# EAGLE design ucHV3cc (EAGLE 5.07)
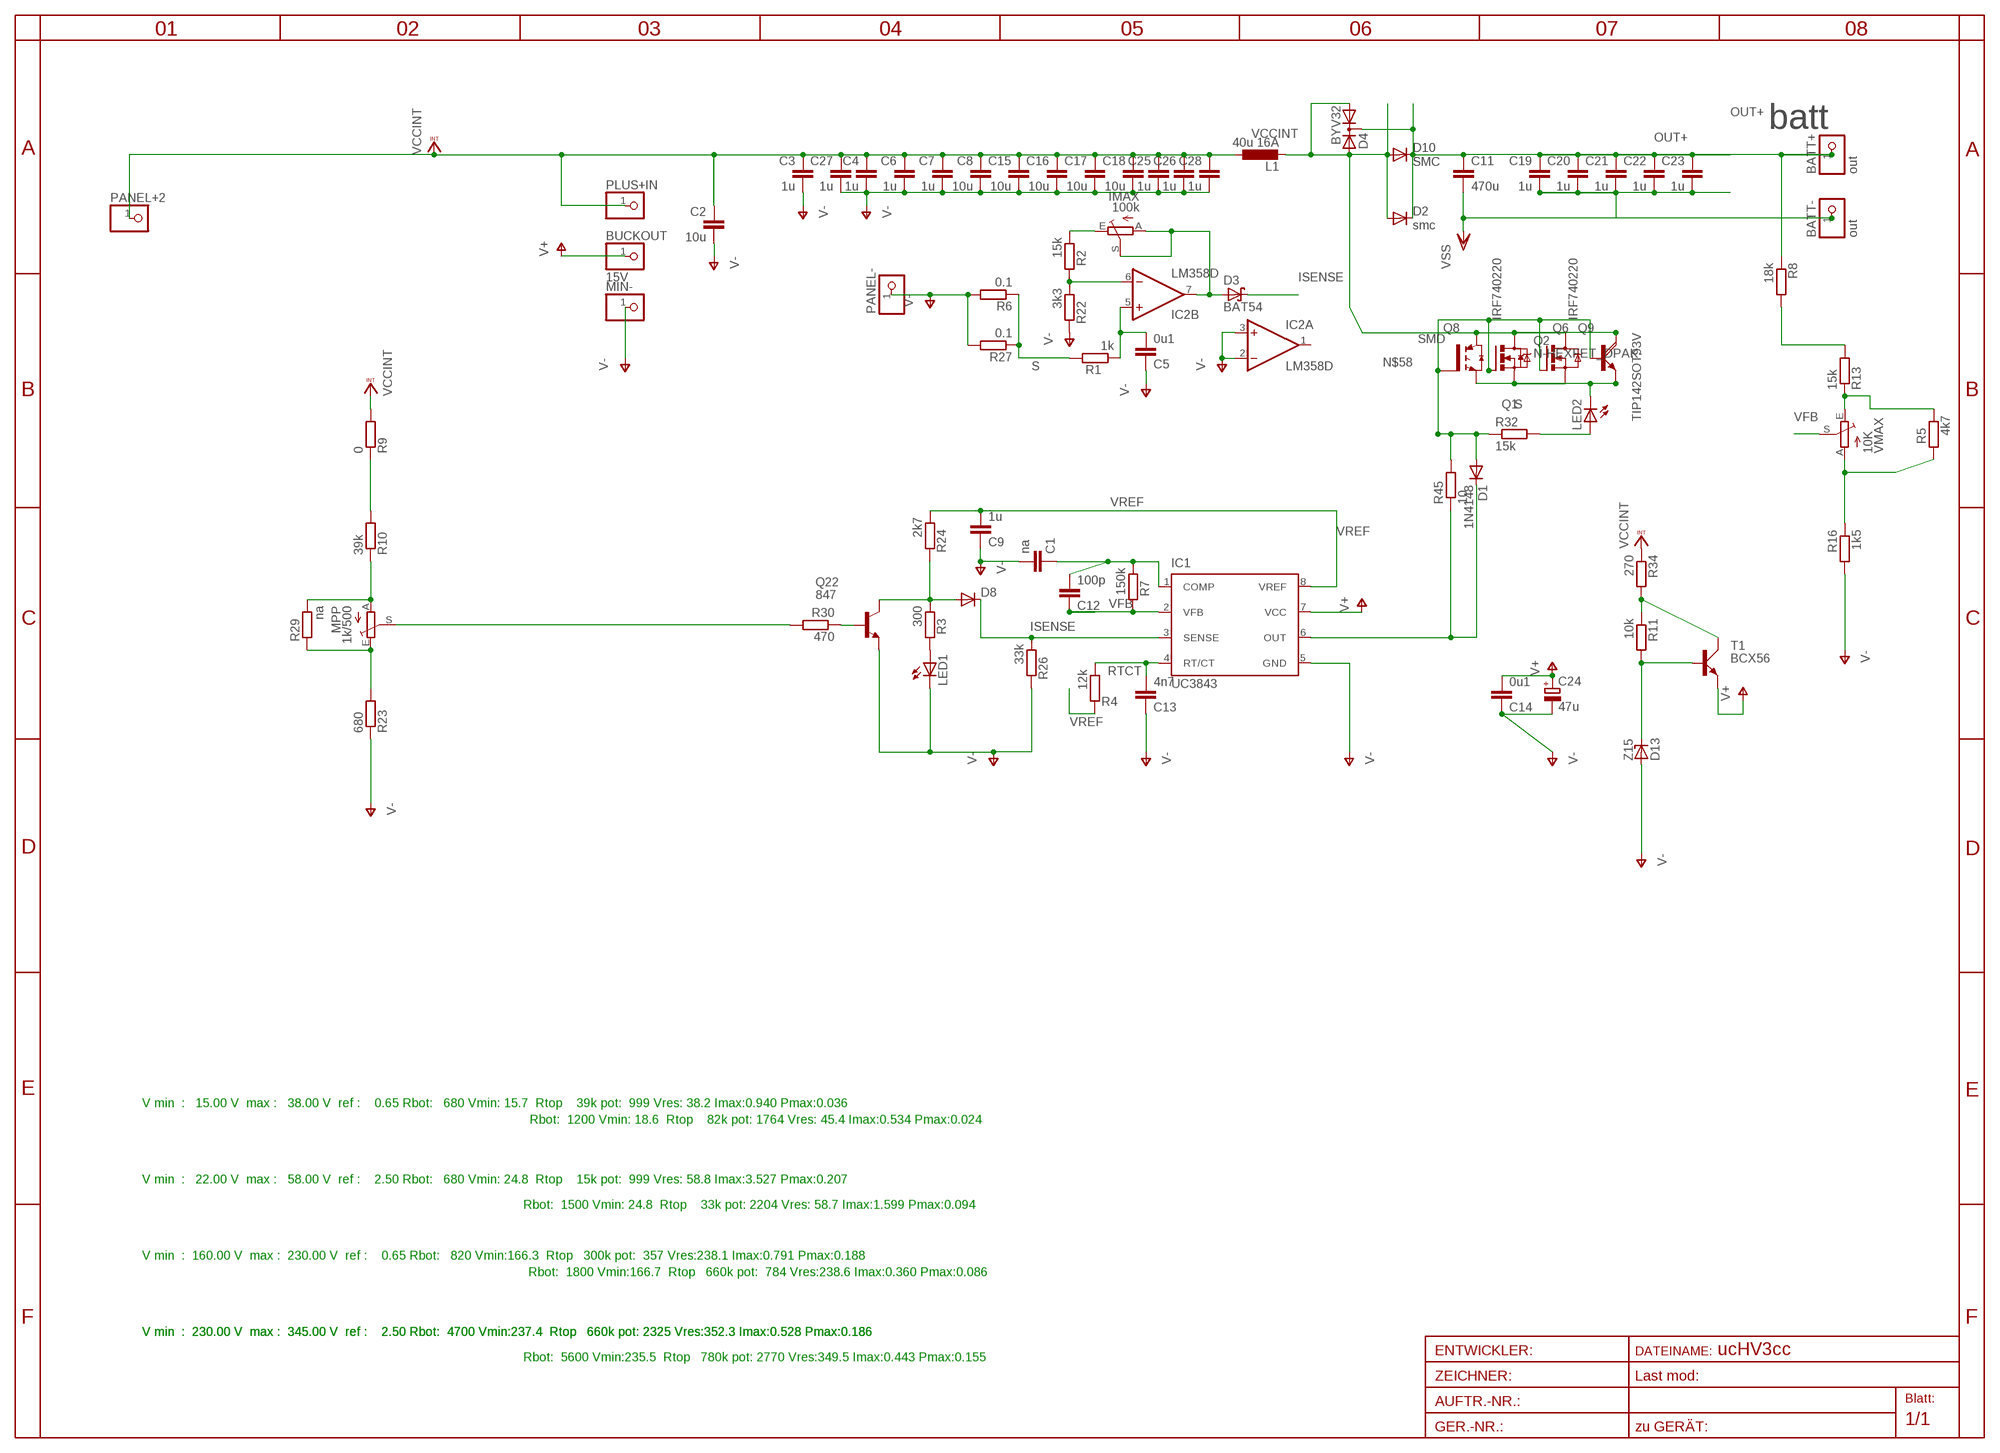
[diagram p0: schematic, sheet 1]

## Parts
BATT+  out  PINHD-1X11MM6  [1X1MM8]
BATT-  out  PINHD-1X11MM6  [1X1MM8]
BUCKOUT  15V  PINHD-1X11MM0  [1X1MM0]
C1  na  C-EUC0805  [C0805]
C2  10u  C-EUC058MLCC  [C058-020X040]
C3  1u  C-EUC058MLCC  [C058-020X040]
C4  1u  C-EUC058MLCC  [C058-020X040]
C5  0u1  C-EUC0805  [C0805]
C6  1u  C-EUC058MLCC  [C058-020X040]
C7  1u  C-EUC058MLCC  [C058-020X040]
C8  10u  C-EUC058MLCC  [C058-020X040]
C9  1u  C-EUC1206  [C1206]
C11  470u  C-EU075-052X106  [C075-052X106]
C12  100p  C-EUC0805  [C0805]
C13  4n7  C-EUC0805  [C0805]
C14  0u1  C-EUC3216  [C3216]
C15  10u  C-EUC058MLCC  [C058-020X040]
C16  10u  C-EUC058MLCC  [C058-020X040]
C17  10u  C-EUC058MLCC  [C058-020X040]
C18  10u  C-EUC058MLCC  [C058-020X040]
C19  1u  C-EUC1206  [C1206]
C20  1u  C-EUC1206  [C1206]
C21  1u  C-EUC1206  [C1206]
C22  1u  C-EUC1206  [C1206]
C23  1u  C-EUC1206  [C1206]
C24  47u  CPOL-EUSANYO_SMD_C6  [SANYO-OSCON_SMD_C6]
C25  1u  C-EUC058MLCC  [C058-020X040]
C26  1u  C-EUC058MLCC  [C058-020X040]
C27  1u  C-EUC058MLCC  [C058-020X040]
C28  1u  C-EUC058MLCC  [C058-020X040]
D1  1N4148  DIODE-MINIMELF  [MINIMELF]
D2  smc  DIODE-SMC  [SMC]
D3  BAT54  [SOT23]
D4  BYV32  [TO220ABS]
D8  DIODE-SOT23  [SOT23]
D10  SMC  DIODE-SMC  [SMC]
D13  Z15  ZENER-DIODESOD80C  [SOD80C]
IC1  UC3843  UC1843D8  [SO-08]
IC2  LM358D  [SO08]
IMAX  100k  TRIM_EU-S64W  [S64W]
L1  40u 16A  L-EU  [RING]
LED1  LEDCHIPLED_1206  [CHIPLED_1206]
LED2  LEDCHIPLED_1206  [CHIPLED_1206]
MIN-  PINHD-1X11MM0  [1X1MM0]
MPP  1k/500  TRIM_EU-S64W  [S64W]
PANEL+2  PINHD-1X11MM6  [1X1MM8]
PANEL-  PINHD-1X11MM6  [1X1MM8]
PLUS+IN  PINHD-1X11MM0  [1X1MM0]
Q1  IRF740220  [TO220BV]
Q2  N-HEXFET_DPAK-  [TO252]
Q6  IRF740220  [TO220BV]
Q8  SMD  IRG4BC15UD-S  [D2PACK]
Q9  TIP142SOT93V  [SOT93V]
Q22  847  BC847ASMD  [SOT23]
R1  1k  R-EU_R0805  [R0805]
R2  15k  R-EU_R0805  [R0805]
R3  300  R-EU_R0805  [R0805]
R4  12k  R-EU_R0805  [R0805]
R5  4k7  R-EU_R0805  [R0805]
R6  0.1  R-EU_0207/10  [0207/10]
R7  150k  R-EU_R0805  [R0805]
R8  18k  R-EU_R1206  [R1206]
R9  0  R-EU_R1206  [R1206]
R10  39k  R-EU_R1206  [R1206]
R11  10k  R-EU_R1206  [R1206]
R13  15k  R-EU_R1206  [R1206]
R16  1k5  R-EU_R0805  [R0805]
R22  3k3  R-EU_R0805  [R0805]
R23  680  R-EU_R0805  [R0805]
R24  2k7  R-EU_R0805  [R0805]
R26  33k  R-EU_R0805  [R0805]
R27  0.1  R-EU_R3216  [R3216]
R29  na  R-EU_R1206  [R1206]
R30  470  R-EU_R0805  [R0805]
R32  15k  R-EU_R0805  [R0805]
R34  270  R-EU_0617/17  [0617/17]
R45  10  R-EU_R0805  [R0805]
T1  BCX56  [SOT223]
VMAX  10K  TRIM_EU-S64W  [S64W]

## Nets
DQ18: D2.A D4.A1 D4.A2 D10.A L1.2 Q1.D Q2.3(D) Q6.D Q8.2(C) Q9.C
ISENSE: D3.3(C) D8.3(C) IC1.3(SENSE) R26.1
N$1: C5.2 IC2.5(B:+IN) R1.1
N$2: IMAX.E R2.1
N$3: Q22.1(B) R30.1
N$4: LED1.A R3.2
N$5: LED2.A R32.2
N$6: R8.2 R13.2
N$7: D13.C R11.2 T1.1(B)
N$18: C1.1 C12.2 IC1.1(COMP) R7.1
N$21: R5.2 R16.1 VMAX.A
N$22: D3.1(A) IC2.7(B:OUT) IMAX.A IMAX.S
N$23: R11.1 R34.2 T1.2(C)
N$25: D1.C IC1.6(OUT) R45.1
N$27: IC2.6(B:-IN) R2.2 R22.1
N$30: R9.1 R10.2
N$32: MPP.A R10.1 R29.1
N$34: MPP.E R23.2 R29.2
N$37: R5.1 R13.1 VMAX.E
N$58: D1.A Q1.G Q2.1(G) Q6.G Q8.1(G) Q9.B R32.1 R45.2
N$71: D8.1(A) Q22.3(C) R3.1 R24.2
OUT+: BATT+.1 C11.1 C19.1 C20.1 C21.1 C22.1 C23.1 D2.C D4.C D10.C R8.1
PRB1: MPP.S R30.2
RTCT: C13.2 IC1.4(RT/CT) R4.1
S: LED2.C Q1.S Q2.2(S) Q6.S Q8.3(E) Q9.E R1.2 R6.1 R27.1
V+: BUCKOUT.1 C14.2 C24.+ IC1.7(VCC) T1.3(E)
V-: BATT-.1 C1.2 C2.2 C3.2 C4.2 C5.1 C6.2 C7.2 C8.2 C9.1 C11.2 C13.1 C14.1 C15.2 C16.2 C17.2 C18.2 C19.2 C20.2 C21.2 C22.2 C23.2 C24.- C25.2 C26.2 C27.2 C28.2 D13.A IC1.5(GND) IC2.2(A:-IN) IC2.3(A:+IN) LED1.C MIN-.1 PANEL-.1 Q22.2(E) R6.2 R16.2 R22.2 R23.1 R26.2 R27.2 ; supply symbol labelled VSS
VCCINT: C2.1 C3.1 C4.1 C6.1 C7.1 C8.1 C15.1 C16.1 C17.1 C18.1 C25.1 C26.1 C27.1 C28.1 L1.1 PANEL+2.1 PLUS+IN.1 R9.2 R34.1
VFB: C12.1 IC1.2(VFB) R7.2 VMAX.S
VREF: C9.2 IC1.8(VREF) R4.2 R24.1
Unconnected: IC2.1(A:OUT)

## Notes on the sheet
- batt
- V min  :   15.00 V  max :   38.00 V  ref :    0.65 Rbot:   680 Vmin: 15.7  Rtop    39k pot:  999 Vres: 38.2 Imax:0.940 Pmax:0.036
- Rbot:  1200 Vmin: 18.6  Rtop    82k pot: 1764 Vres: 45.4 Imax:0.534 Pmax:0.024
- V min  :   22.00 V  max :   58.00 V  ref :    2.50 Rbot:   680 Vmin: 24.8  Rtop    15k pot:  999 Vres: 58.8 Imax:3.527 Pmax:0.207
- Rbot:  1500 Vmin: 24.8  Rtop    33k pot: 2204 Vres: 58.7 Imax:1.599 Pmax:0.094
- V min  :  160.00 V  max :  230.00 V  ref :    0.65 Rbot:   820 Vmin:166.3  Rtop   300k pot:  357 Vres:238.1 Imax:0.791 Pmax:0.188
- Rbot:  1800 Vmin:166.7  Rtop   660k pot:  784 Vres:238.6 Imax:0.360 Pmax:0.086
- V min  :  230.00 V  max :  345.00 V  ref :    2.50 Rbot:  4700 Vmin:237.4  Rtop   660k pot: 2325 Vres:352.3 Imax:0.528 Pmax:0.186 | V min  :  230.00 V  max :  345.00 V  ref :    2.50 Rbot:  4700 Vmin:237.4  Rtop   660k pot: 2325 Vres:352.3 Imax:0.528 Pmax:0.186
- Rbot:  5600 Vmin:235.5  Rtop   780k pot: 2770 Vres:349.5 Imax:0.443 Pmax:0.155

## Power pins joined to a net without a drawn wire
V+: IC2.8(P:V+)
V-: IC2.4(P:V-)

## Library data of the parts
BATT+ BATT- BUCKOUT MIN- PANEL+2 PANEL- PLUS+IN = pinhead:PINHD-1X1: PIN HEADER
C1-C9 C11-C23 C25-C28 = rcl:C-EU: CAPACITOR, European symbol
C24 = rcl:CPOL-EU: POLARIZED CAPACITOR, European symbol
D1 D2 D8 D10 = diode:DIODE-: DIODE
D3 = diode:BAT54: Schottky Diodes
D4 = diode:BYV32: DIODE 2 x Si diode 200 V, 20 A/230 Apeak, 25 ns
D13 = diode:ZENER-DIODE: Z-Diode
IC1 = texas:UC1843D8: PULSE WIDTH MODULATOR
IC2 = linear:LM358: OP AMP also LM158; LM258; LM2904 Source: http://cache.national.com/ds/LM/LM158.pdf
IMAX MPP VMAX = pot:TRIM_EU-: POTENTIOMETER
L1 = rcl:L-EU: INDUCTOR, European symbol
LED1 LED2 = led:LED: LED
Q1 Q6 = transistor-power:IRF740: N-CHANNEL MOS FET
Q2 = transistor-power:N-HEXFET_?-*: HEXFET® Power MOSFET
Q8 = transistor-power:IRG4BC15UD-: INSULATED GATE BIPOLAR TRANSISTOR WITH ULTRAFAST SOFT RECOVERY DIODE
Q9 = transistor-power:TIP142: NPN DARLINGTON TRANSISTOR
Q22 = transistor-npn:BC847*: NPN Transistor
R1-R10 R13 R16 R22-R24 R26 R27 R29 R30 R34 = rcl:R-EU_: RESISTOR, European symbol
R11 R32 R45 = rcl-2:R-EU_: RESISTOR, European symbol
T1 = transistor-power:BCX56

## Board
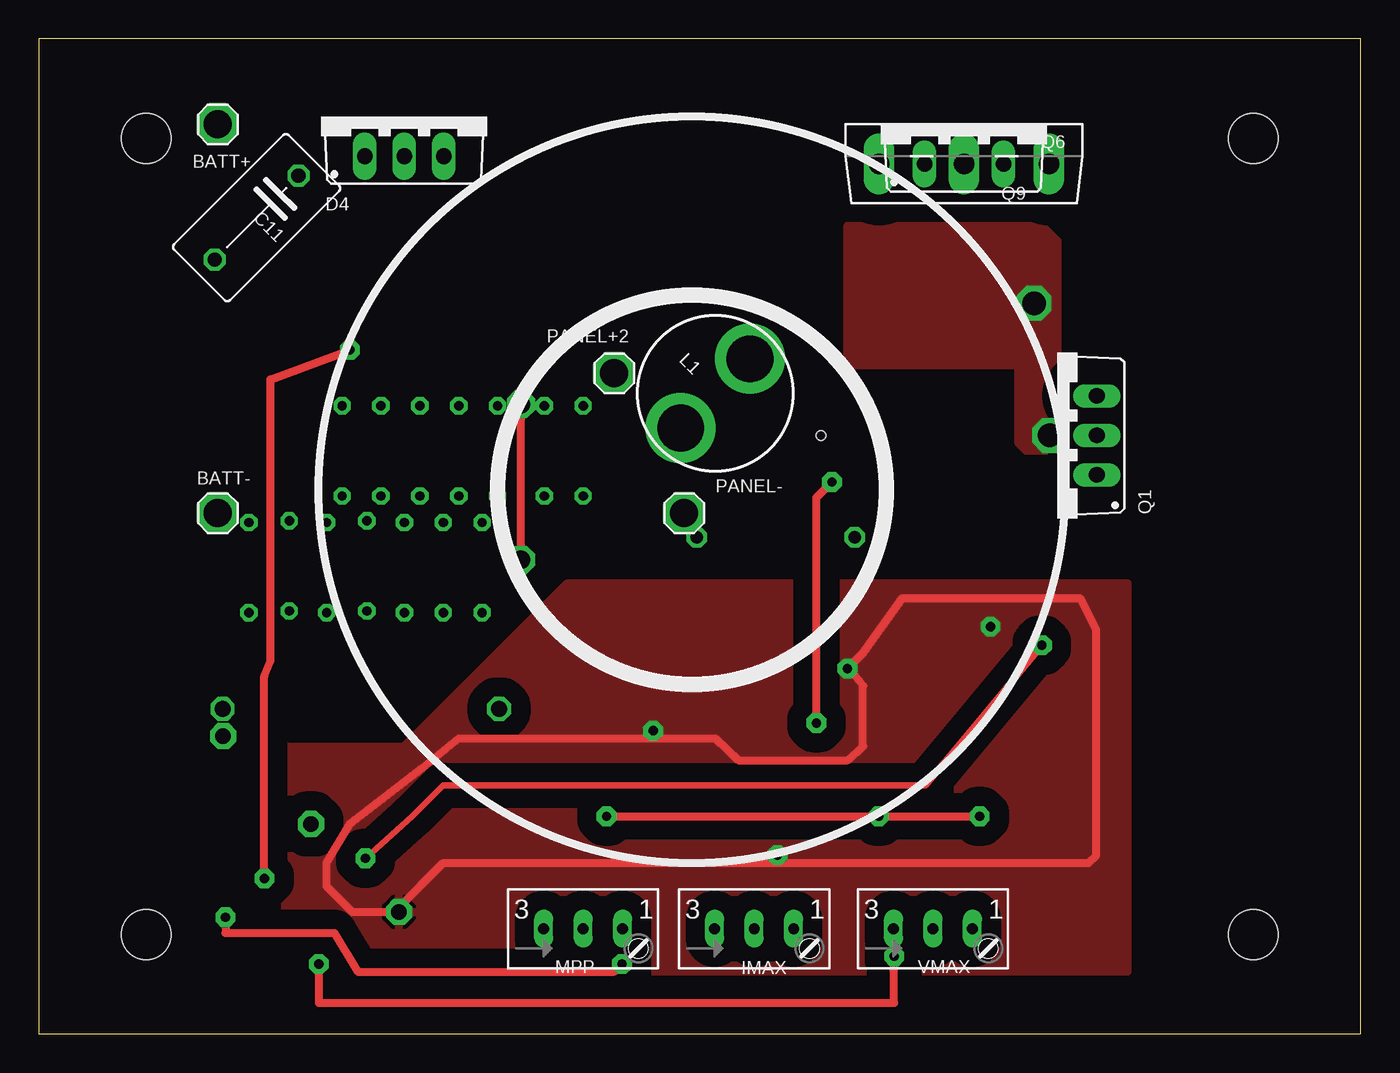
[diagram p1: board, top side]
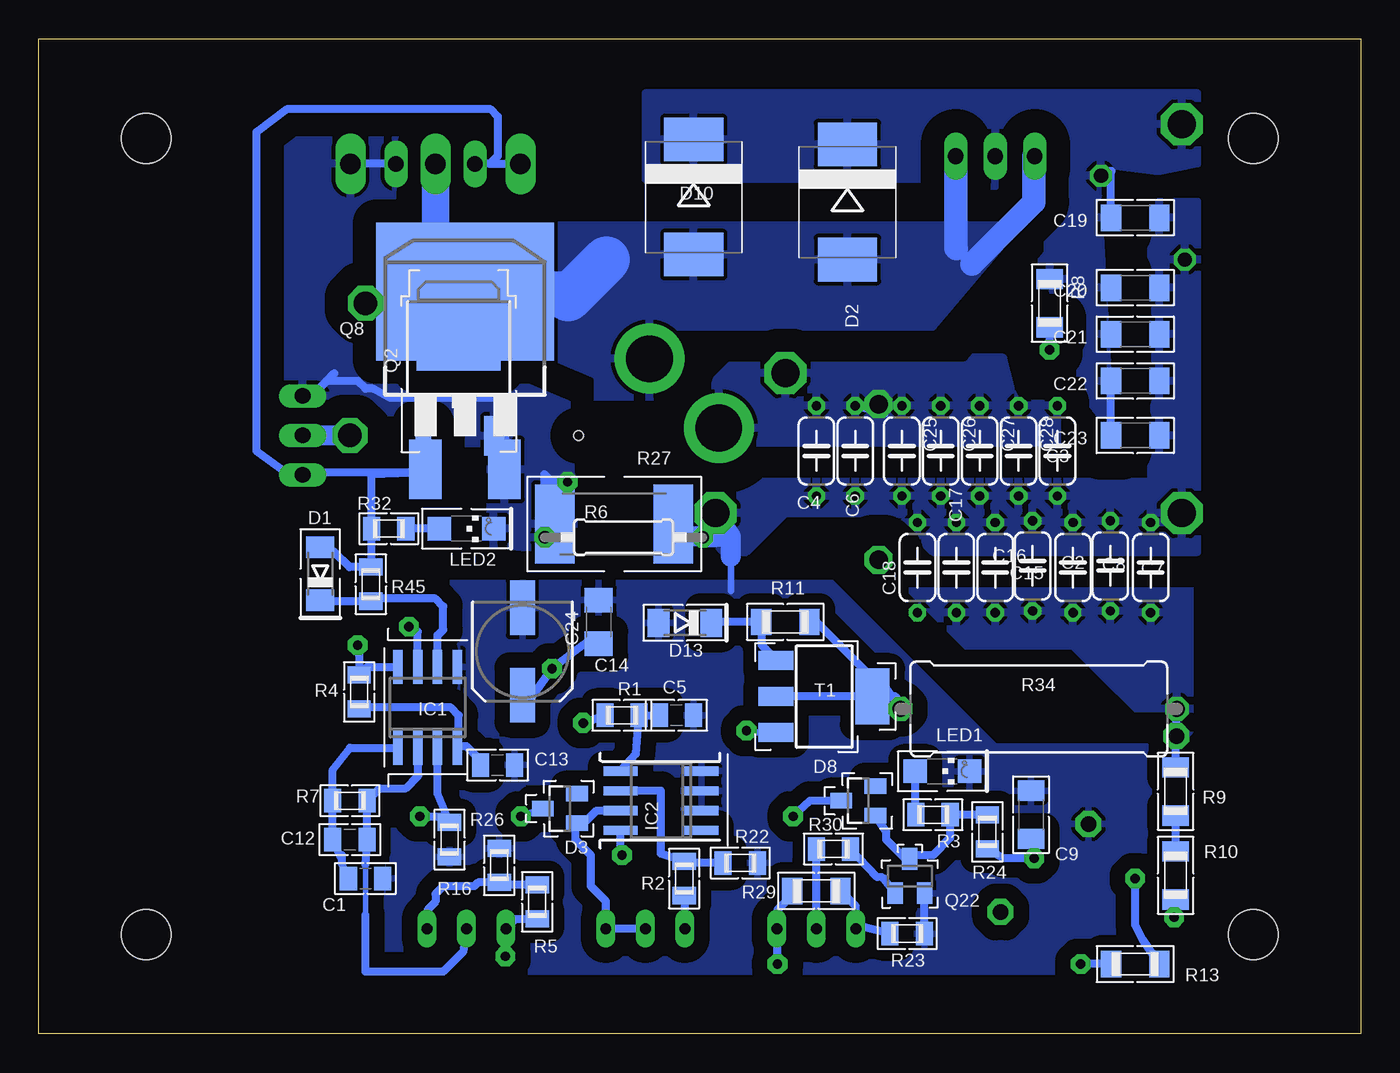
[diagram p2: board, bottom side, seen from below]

Size 85 x 64 mm. Coordinates in mm from the lower left corner, seen from the top.
Outline: 0,0 85,0 85,64 0,64 0,0
Copper layers (1*16): Top 0.035mm / dielectric 1.5mm / Bottom 0.035mm
Design rules "default *": minimum track width 10mil, minimum drill 24mil, track to track 8mil, track to pad 8mil, pad to pad 8mil, via to via 8mil, smd to smd 8mil, copper to edge 1mm, drill to drill 8mil, minimum pad ring 10mil, minimum via ring 8mil, stop-mask expansion 4mil, vias tented up to drill 0mil, thermal gap 10mil
Holes 3.2 mm at 6.9,57.6 6.9,6.4 78.1,6.4 78.1,57.6
Holes 0.6 mm at 50.3,38.5

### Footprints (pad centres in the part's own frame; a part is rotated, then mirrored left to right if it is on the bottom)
1X1MM8 = drill 1.8 pad 2.54 octagon: 1 0,0
1X1MM0 = drill 1 pad 1.676 octagon: 1 0,0
C0805 = smd 1.1 x 1.5: 1 -1.1,0; 2 1.1,0
C058-020X040 = drill 0.6 octagon: 1 -2.9,0; 2 2.9,0
C1206 = smd 1.3 x 1.7: 1 -1.55,0; 2 1.55,0
C075-052X106 = drill 0.914 octagon: 1 -3.81,0; 2 3.81,0
C3216 = smd 1.6 x 1.8: 1 -1.4,0; 2 1.4,0
SANYO-OSCON_SMD_C6 = smd 3.5 x 1.6: + 2.8,0; - -2.8,0
MINIMELF = smd 1.4 x 1.8: A 1.7,0; C -1.7,0
SMC = smd 2.8 x 3.8: A 3.7,0; C -3.7,0
SOT23 = smd 1 x 1.4: 1 -0.95,-1.1; 2 0.95,-1.1; 3 0,1.1
TO220ABS = drill 1.016 long: A1 -2.54,-2.54; A2 2.54,-2.54; C 0,-2.54
SOD80C = smd 1.4 x 1.8: A 1.7,0; C -1.7,0
SO-08 = smd 0.6 x 2.2: 1 -1.905,-2.6; 2 -0.635,-2.6; 3 0.635,-2.6; 4 1.905,-2.6; 5 1.905,2.6; 6 0.635,2.6; 7 -0.635,2.6; 8 -1.905,2.6
SO08 = smd 0.6 x 2.2: 1 -1.905,-2.6; 2 -0.635,-2.6; 3 0.635,-2.6; 4 1.905,-2.6; 5 1.905,2.6; 6 0.635,2.6; 7 -0.635,2.6; 8 -1.905,2.6
S64W = drill 0.7 long: A 2.54,1.27; E -2.54,1.27; S 0,1.27
RING = drill 3 pad 4 round: 1 -3.15,0; 2 3.15,0
CHIPLED_1206 = smd 1.5 x 1.5: A 0,-1.75; C 0,1.75
TO220BV = drill 1.016 long: D 0,-2.54; G -2.54,-2.54; S 2.54,-2.54
TO252 = smd 1 x 1.6: 1 -2.28,-3.53 | smd 1.27 x 2.54: 2 2.28,-3.53 | smd 5.4 x 6.2: 3 0,3.77
D2PACK = smd 2.083 x 3.81: 1 -2.54,-8.89; 3 2.54,-8.89 | smd 11.43 x 8.89: 2 0,2.54
SOT93V = drill 1.3 pad 1.676 long: B -5.461,-2.54; C 0,-2.54; E 5.461,-2.54
R0805 = smd 1.1 x 1.5: 1 -1.1,0; 2 1.1,0
0207/10 = drill 0.813 octagon: 1 -5.08,0; 2 5.08,0
R1206 = smd 1.3 x 1.7: 1 -1.55,0; 2 1.55,0
R3216 = smd 2.54 x 5.08: 1 -3.81,0; 2 3.81,0
0617/17 = drill 1.016 octagon: 1 -8.89,0; 2 8.89,0
SOT223 = smd 1.219 x 2.235: 1 -2.311,-3.099; 2 0,-3.099; 3 2.311,-3.099 | smd 3.6 x 2.2: 4 0,3.099

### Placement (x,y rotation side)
BATT+  11.5,58.5 0 top
BATT-  11.5,33.5 0 top
BUCKOUT  23.16,7.84 90 top
C1  64,10 0 bottom
C2  18.5,30 90 bottom
C3  19.5,37.5 270 bottom
C4  35,37.5 270 bottom
C5  44,20.5 180 bottom
C6  32.5,37.5 270 bottom
C7  13.5,30 90 bottom
C8  16.1,30.1 90 bottom
C9  21.2,14.1 270 bottom
C11  14,52.5 225 top
C12  65,12.5 180 bottom
C13  55.5,17.3 180 bottom
C14  49,26.5 270 bottom
C15  21.1,30.1 90 bottom
C16  23.5,30 90 bottom
C17  26,30 90 bottom
C18  28.5,30 90 bottom
C19  14.5,52.5 0 bottom
C20  14.5,48 0 bottom
C21  14.5,45 0 bottom
C22  14.5,42 0 bottom
C23  14.5,38.5 0 bottom
C24  53.9,24.6 270 bottom
C25  29.5,37.5 270 bottom
C26  27,37.5 270 bottom
C27  24.5,37.5 270 bottom
C28  22,37.5 270 bottom
D1  66.9,29.6 90 bottom
D2  33,53.5 270 bottom
D3  51.5,14.5 90 bottom
D4  23.5,59 0 top
D8  32.3,15 90 bottom
D10  42.89,53.83 270 bottom
D13  43.46,26.45 180 bottom
IC1  60,21 0 bottom
IC2  45,15 90 bottom
IMAX  46,5.5 0 top
L1  43.5,41.2 45 top
LED1  26.9,16.9 270 bottom
LED2  57.5,32.5 270 bottom
MIN-  17.5,13.5 315.7 top
MPP  35,5.5 0 top
PANEL+2  37,42.5 0 top
PANEL-  41.5,33.5 90 top
PLUS+IN  11.84,19.16 90 top
Q1  65.5,38.5 90 top
Q2  58,42 0 bottom
Q6  59.5,58.5 0 top
Q8  57.6,45.2 0 bottom
Q9  59.5,58.5 0 top
Q22  28.99,10.16 0 bottom
R1  47.5,20.5 180 bottom
R2  43.5,10 90 bottom
R3  27.5,14.1 180 bottom
R4  64.4,22 90 bottom
R5  52.95,8.5 90 bottom
R6  47.4,31.95 0 bottom
R7  65,15 0 bottom
R8  20,47 270 bottom
R9  11.9,15.6 90 bottom
R10  11.9,10.2 90 bottom
R11  37,26.5 180 bottom
R13  14.5,4.5 0 bottom
R16  55.4,10.85 90 bottom
R22  39.9,11 0 bottom
R23  29.16,6.46 180 bottom
R24  24,13 90 bottom
R26  58.6,12.5 270 bottom
R27  48,32.8 0 bottom
R29  35,9.2 0 bottom
R30  33.9,11.9 180 bottom
R32  62.5,32.5 0 bottom
R34  20.7,20.9 180 bottom
R45  63.65,28.93 90 bottom
T1  34.5,21.7 270 bottom
VMAX  57.5,5.5 0 top

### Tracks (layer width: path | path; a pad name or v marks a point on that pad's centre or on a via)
DQ18  (via drill 1.5 pad 1.2)
  Bottom 0.406: v64,47 58.9,47 58.9,47.89
  Bottom 0.5: Q2.3 58,46.1 58.9,47
  Bottom 1.27: v65,38.5 Q1.D
  Bottom 1.5: D4.A1 21,56.46 21,53.5 25,49.5 | D4.A2 26.04,50.54 26,50.5
  Bottom 1.778: 59.5,48.04 Q9.C
  Bottom 2.54: Q8.2 58.9,47.89 59.5,48.04
  Bottom 3: Q8.2 51.04,47.54 50.97,47.34 48.51,49.8
  pour Bottom (isolate 1.5, rank 2): 22,52 53,52 52,43 49.5,41 44.5,41 44.5,45.5 27.5,45.5
  pour Top (isolate 2): 52,52 64.5,52 65.5,51 65.5,38 65,37.5 63.5,37.5 63,38 63,43 52.5,43 52,43.5
ISENSE  (via drill 0.6 pad 1.27)
  Top 0.5: v36.5,14 v54,14 v60.5,14
  Bottom 0.406: v54,14 D3.3
  Bottom 0.5: IC1.3 59.37,15.46 R26.1 59,14 v60.5,14 | D8.3 35.4,15 v36.5,14
N$1
  Bottom 0.5: IC2.5 46.6,18 R1.1 C5.2
N$2
  Bottom 0.5: IMAX.E 43.46,8.86 R2.1
N$3
  Bottom 0.5: Q22.1 30.76,10.06 31.1,10.1 R30.1
N$4
  Bottom 0.5: R3.2 LED1.A
N$5
  Bottom 0.5: LED2.A R32.2
N$6  (via drill 0.6 pad 1.27)
  Top 0.5: v14.5,10 14.5,23 14.9,24 14.9,42.1 v20,44
  Bottom 0.5: v20,44 R8.2 | v14.5,10 14.5,7 14,6.05 R13.2
N$7
  Bottom 0.5: T1.1 37.6,24.1 38.5,25 38.5,26.45 R11.2 41.7,26.5 D13.C
N$18
  Bottom 0.5: C1.1 65.5,10.95 65.5,11.5 65.6,11.4 C12.2 R7.1 66.1,17 65,18.4 IC1.1
N$21
  Bottom 0.5: R5.2 55.25,9.6 R16.1 56.75,9.75 57,9.5 59,9.5 59.5,9 59.5,8.5 60,8 60,6.81 VMAX.A
N$22
  Bottom 0.5: IMAX.S IMAX.A 48.54,8.54 49.5,9.5 49.5,11.5 50.5,12.5 50.5,13.45 D3.1 50.35,13.5 50,13.5 49.13,14.37 IC2.7
N$23
  Bottom 0.5: T1.2 29.89,21.7 R34.2 30.69,22.5 31,22.5 35,26.5 R11.1
N$25
  Bottom 0.5: IC1.6 59.37,25.64 59,26 59,27.5 59.5,28 63.48,28 R45.1 66.83,27.83 D1.C
N$27
  Bottom 0.5: IC2.6 45,15.63 45,11.6 R2.2 43.4,11 R22.1
N$30
  Bottom 0.5: R10.2 R9.1
N$32  (via drill 0.6 pad 1.27)
  Top 0.5: v12,7.5 12,6.5 19,6.5 20.5,4 37,4 v37.5,4.5
  Bottom 0.406: MPP.A 37.54,7.04
  Bottom 0.5: R29.1 36.55,8.95 37.5,8 37.5,6.81 MPP.A 37.5,6.73 v37.5,4.5 | R10.1 11.9,7.6 v12,7.5
N$34
  Bottom 0.5: R23.2 32.27,6.96 MPP.E 32.46,8.21 R29.2
N$37  (via drill 0.6 pad 1.27)
  Top 0.5: v18,4.5 18,2 55,2 v55,5 | VMAX.E 55,6.73
  Bottom 0.5: VMAX.E 54.9,6.83 | R5.1 54.33,7.4 VMAX.E | R13.1 v18,4.5 | v55,5 55,6.73 VMAX.E
N$58
  Bottom 0.406: Q1.G 68.5,36.46 68.5,36.11
  Bottom 0.5: 56,55.96 Q9.B | 56,55.96 Q6.G | 61,36.11 Q8.1 60.14,38.33 Q2.1 | 61,36.11 68.5,36.11 69.11,36.11 71,37.5 71,58 69,59.5 56,59.5 55.5,59 55.5,56.46 56,55.96 | 61,36.11 63.6,36.01 R32.1 63.6,30.08 R45.2 65.03,30.03 66,31 66.6,31 D1.A
N$71
  Bottom 0.5: R24.2 R3.1 26.4,12.6 27.5,11.5 28.75,11.5 Q22.3 29.26,11.26 30.5,12.5 30.5,13 D8.1
OUT+
  Bottom 0.5: C23.1 C22.1 | C19.1 16.05,55.45 16,55.5 16.39,55.5 C11.1
  pour Bottom (isolate 1.5, rank 4): 10.5,56 10.5,60.5 46,60.5 46,55 26,55 20,49 19,42 arc46 16,38 17,56 13,55.5
PRB1
  Bottom 0.5: MPP.S R30.2
RTCT
  Bottom 0.5: R4.1 64.5,21 58.5,21 58,20.5 58,18.5 IC1.4 57.99,18.5 57.5,18.5 56.6,17.6 C13.2
S  (via drill 0.6 pad 1.27)
  Top 0.5: v50,20 50,34.5 v51,35.5
  Bottom 0.5: Q6.S Q9.E | 54.61,36.11 Q8.3 55,36.37 55,40 55.4,40.9 62.4,40.9 63.5,41.5 64,41.5 64.5,42 66.5,42 | Q1.S 66.96,41.54 66.5,42 | 66.5,42 66,42.5 | v50,20 R1.2 | v51,35.5 52,35.5 52.5,36 52.5,31.97 R6.1
  Bottom 1.27: R6.1 51.81,31.95 R27.1
  pour Bottom (isolate 1.5): 62,58 70.5,58 71,57.5 71,39 69.5,39 68.5,40 62.5,40 60.5,38 56,38 56,31.5 50.5,31 51,40.5 54.5,42 62.5,42 63,42.5
V+  (via drill 0.6 pad 1.27)
  Top 0.5: v52,23.5 53,24.5 55.5,28 67,28 68,26 68,11.5 67.5,11 26,11 23,8 | BUCKOUT.1 20.16,7.84 18.5,9.5 18.5,11 20,13.5 24.5,17 27,19 43.5,19 45,17.6 52,17.6 53,18.5 53,22.42 52.11,23.52 | v39.5,19.5 39.5,19
  Bottom 0.406: T1.3 39.5,19.39 v39.5,19.5
  Bottom 0.5: C14.2 49.9,25.1 v52,23.5 53.3,21.7 C24.+ | IC1.7 60.63,25.86 v61.2,26.2 | IC2.8 47.6,11.4 v47.5,11.5
  pour Top (isolate 1.25): 34,29 70,29 70,4 12,4 12,18.5 23.5,18.5
V-
  Bottom 0.406: 40.5,28.5 40.5,30.7
  Bottom 0.5: R23.1 28,6.5 28,6 28.04,6.97 Q22.2
  Bottom 1.27: 40.5,32 PANEL-.1 | 40.5,30.7 40.5,32 | 40.5,32 41,32 | 41,32 44.19,32 R27.2 | R6.2 41.5,31.95 41,32
  pour Bottom (isolate 1): 34,29 70,29 70,4 12,4 12,18.5 23.5,18.5
  pour Bottom (isolate 2): 10.5,53.5 13,53.5 13.5,53 13.5,35.5 41.5,35.5 41.5,31.5 41,31 39.5,31 37,33.5 30,33.5 27.5,31 10.5,31
VCCINT  (via drill 1.2)
  Top 0.5: v31,30.5 v31,40.5
  Bottom 0.5: R34.1 11.84,21.37 PLUS+IN.1 11.9,19.1 R9.2 | C6.1 30.6,39.9 v31,40.5
  pour Bottom (isolate 2, rank 2): 11,29 27.5,29 30.5,32.5 37.5,32.5 37.5,30 34,30 29,25 18.5,25 12.5,19 11.5,19 11,19.5
  pour Bottom (isolate 2, rank 3): 23,43.5 40,43.5 44.5,39 44.5,36.5 37,36.5 36.5,37 19.5,37.5 19.5,40.5 22,40.5 22.5,41.5
VFB
  Bottom 0.35: 64,7.63 64,10.9
  Bottom 0.5: VMAX.S 57.7,5.29 59,4 64,4 64,7.63 | 64,10.9 63.9,12.16 C12.1 R7.2 63.1,15.8 61.4,15.8 60.6,16.6 60.6,17.36 IC1.2
VREF  (via drill 0.6 pad 1.27)
  Top 0.406: v64.5,25 57,16 26,16 24,14 v21,11.3
  Bottom 0.5: R24.1 23,11.3 v21,11.3 21,12.35 C9.2 | IC1.8 63.9,23.6 R4.2 64.4,24.4 64.5,24.5 v64.5,25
